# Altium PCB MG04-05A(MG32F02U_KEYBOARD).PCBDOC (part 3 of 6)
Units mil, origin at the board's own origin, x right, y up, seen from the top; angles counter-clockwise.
Board outline 17912.8 x 10422.68 mil, 2 copper layers (Top Layer, Bottom Layer); 623 components, 347 nets, 1816 pads, 821 vias.
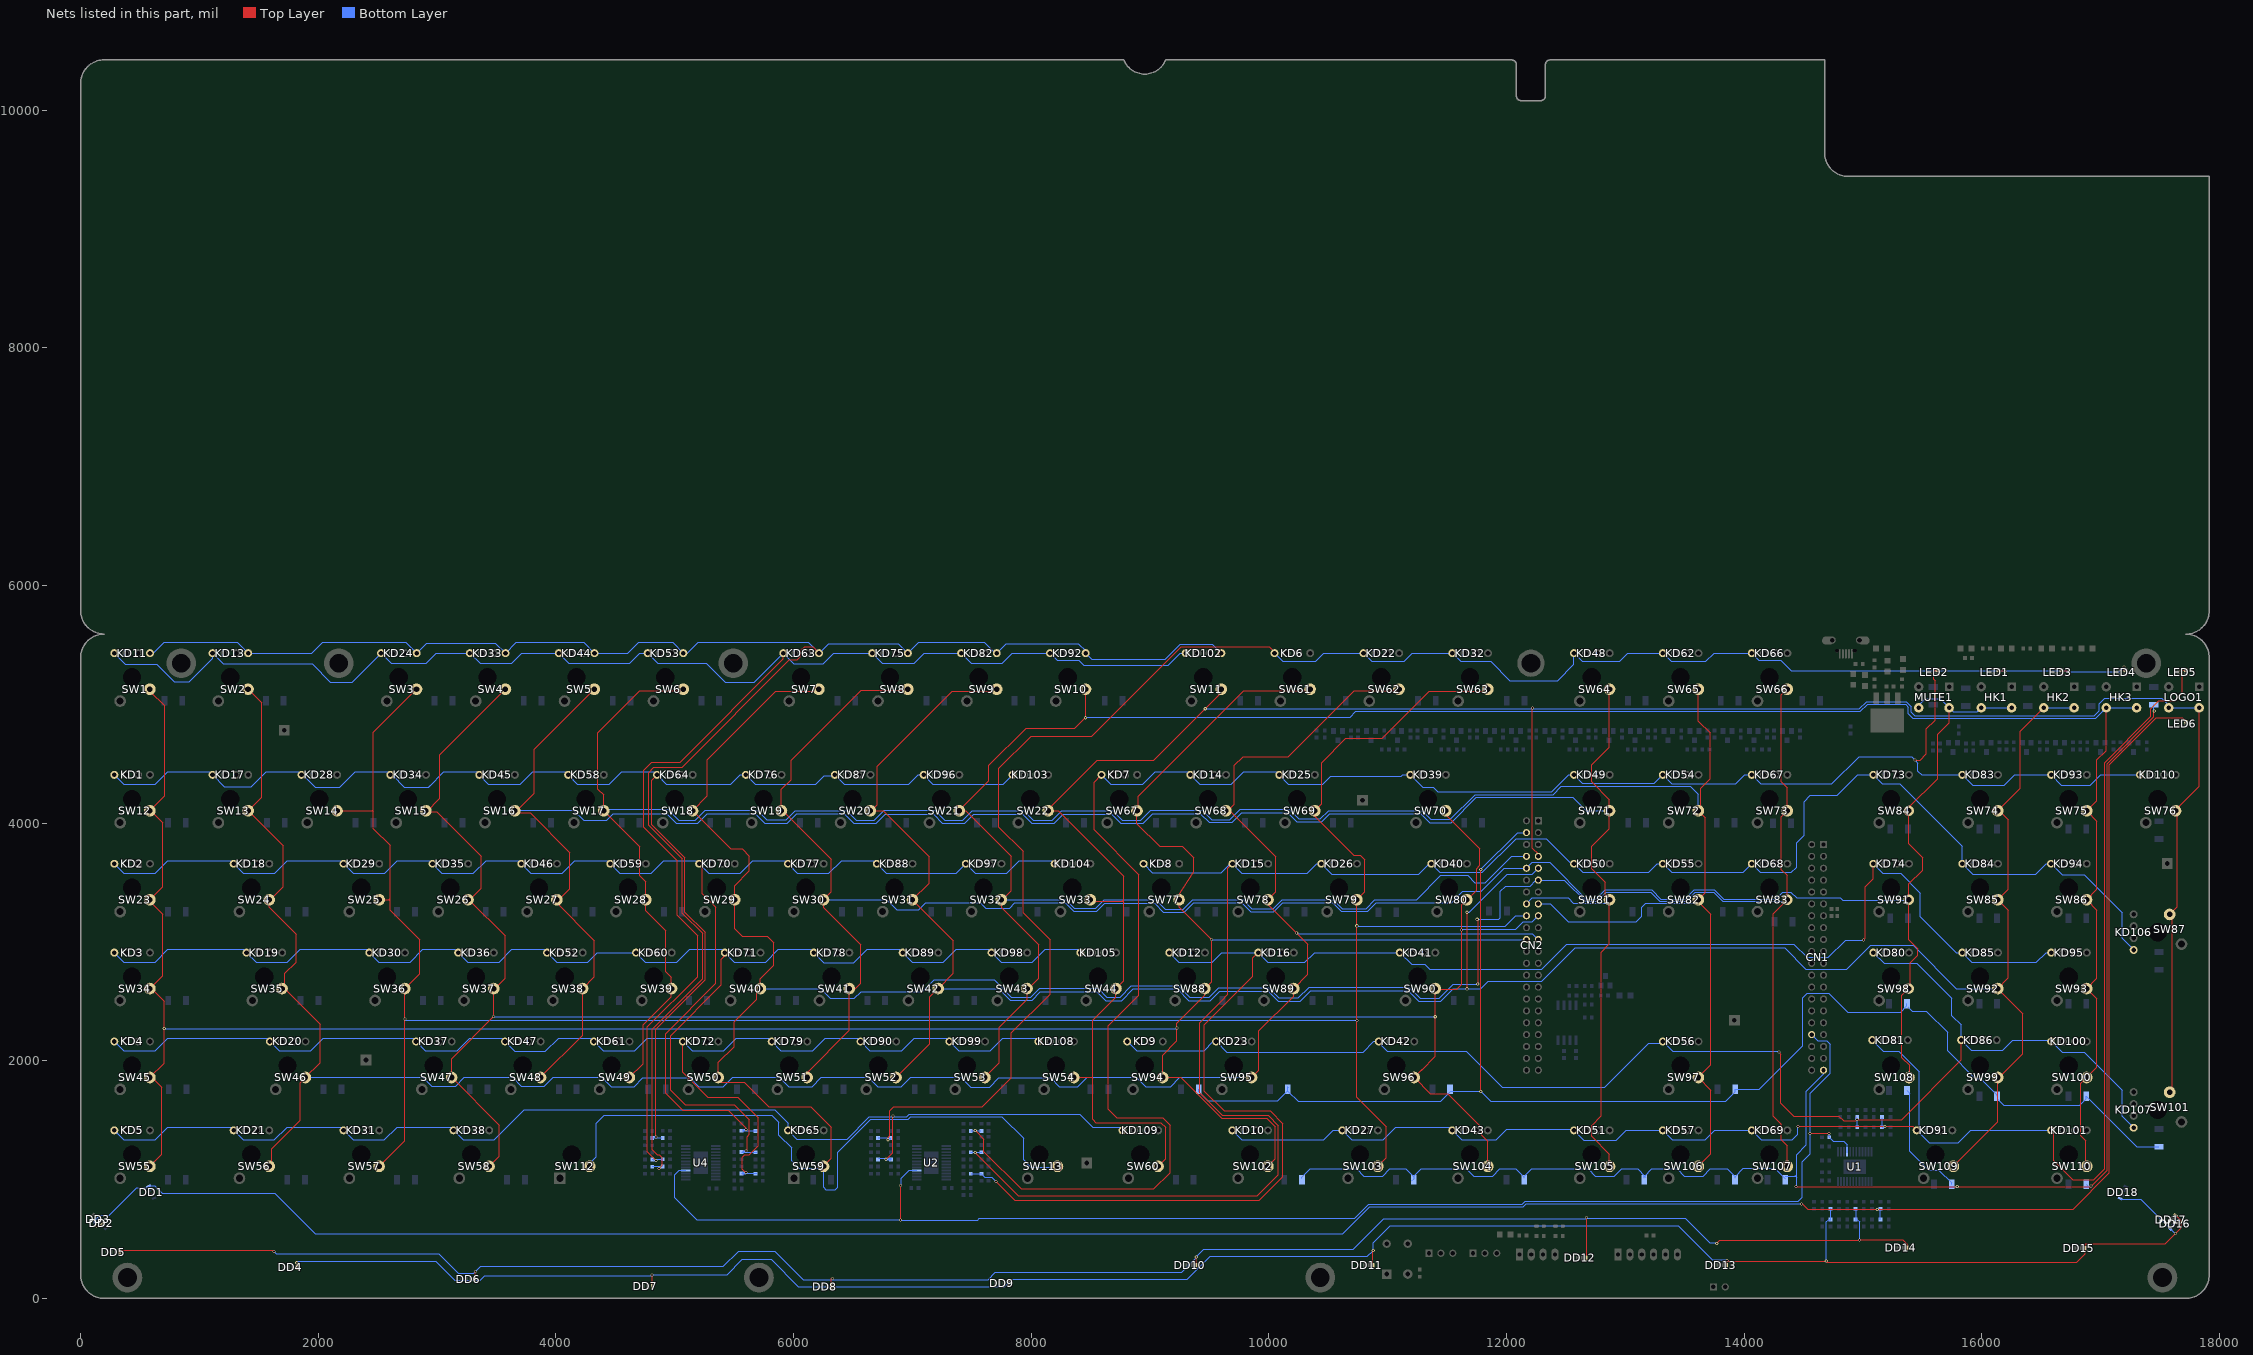
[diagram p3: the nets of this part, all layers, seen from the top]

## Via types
v1: diameter 30, hole 12, Top Layer to Bottom Layer, tented both sides, 273 vias
v2: diameter 26, hole 16, Top Layer to Bottom Layer, tented both sides, 181 vias
v3: diameter 26, hole 12, Top Layer to Bottom Layer, tented both sides, 165 vias
v4: diameter 33, hole 20, Top Layer to Bottom Layer, tented both sides, 61 vias
v5: diameter 25, hole 12, Top Layer to Bottom Layer, tented both sides, 47 vias
v6: diameter 20, hole 12, Top Layer to Bottom Layer, tented both sides, 40 vias
v7: diameter 30, hole 16, Top Layer to Bottom Layer, tented both sides, 30 vias
v8: diameter 28, hole 16, Top Layer to Bottom Layer, tented both sides, 12 vias
v9: diameter 35, hole 20, Top Layer to Bottom Layer, tented both sides, 5 vias
v10: diameter 25, hole 16, Top Layer to Bottom Layer, tented both sides, 3 vias
v11: diameter 40, hole 12, Top Layer to Bottom Layer, tented both sides, 3 vias
v12: diameter 40, hole 20, Top Layer to Bottom Layer, tented both sides, 1 vias

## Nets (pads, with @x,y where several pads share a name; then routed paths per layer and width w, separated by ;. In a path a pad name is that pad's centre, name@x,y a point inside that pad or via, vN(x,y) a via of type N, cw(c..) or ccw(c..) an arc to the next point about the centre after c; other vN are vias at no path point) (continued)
KB_C10: CN2.4 D101.2 D102.2 D103.2 D104.2 D105.2 D106.2 D107.2 D108.2 | length 12067.7
  Top Layer w8: v2(11782,1742.74) v2(11782,3610)
  Bottom Layer w8: D101.2@9408.69,1759.19 9408.69,1739.78 9485.73,1662.74 10073.27,1662.74 D102.2@10158.58,1748.05 ; D102.2@10158.58,1779.28 D102.2@10158.58,1775.43 ; D102.2@10161.56,1776.29 10160.5,1777.35 D102.2@10158.58,1775.43 ; v2(11782,3610) 12092,3920 CN2.4@12167,3920 ; D105.2@15367.95,2480 15367.95,2462.42 15315.34,2409.8 14870.68,2409.8 14712,2568.48 14529.6,2568.48 14492,2530.88 14492,2126.47 14124.72,1759.19 D104.2@13923.88,1759.19 13923.88,1737.74 13844.22,1658.07 11867,1658.07 11782.33,1742.74 v2(11782,1742.74) 11529.74,1742.74 11445.07,1658.07 10245.39,1658.07 10158.58,1744.89 D102.2@10158.58,1748.05 ; D105.2@15377.35,2454.8 15413.52,2418.63 15532.35,2418.63 15710.49,2240.49 15710.49,2082.66 15943.15,1850 15988.47,1850 16127.95,1710.51 D106.2@16127.95,1700 ; D106.2@16127.95,1680.2 16183.15,1625 16823.15,1625 16877.95,1679.8 D107.2@16877.95,1700 17301.51,1276.45 D108.2@17489.6,1276.45 ; D102.2@10158.58,1748.05 D102.2@10158.58,1759.19 D102.2@10158.58,1775.43
KB_C11: CN1.39 D109.2 D110.2 D111.2 D112.2 D113.2 D114.2 D115.2 D116.2 D117.2 D118.2 | length 13746
  Top Layer w8: v2@14437,941.47 v2(15792,941.47) v2@16918.15,941.47 ; v2(16918.15,945) 17053.15,1080 17053.15,4501 17447,4894.85 v2@17447,4944.7
  Bottom Layer w8: D109.2@10277.95,1011.2 10277.95,1020.95 10347,1090 10737,1090 10797,1030 10957,1030 11017,1090 11152,1090 11222,1020 D110.2@11223.57,1020 ; D110.2@11201.85,989.48 D110.2@11220.76,1008.39 ; D110.2@11217.95,1011.2 D110.2@11220.76,1008.39 ; D111.2@12147.2,1020 12077.2,1090 11942.2,1090 11882.2,1030 11722.2,1030 11662.2,1090 11282,1090 11223.57,1031.57 D110.2@11223.57,1020 ; D111.2@12148.36,1010.79 12148.77,1011.2 D111.2@12148.77,1028.29 ; D111.2@12150.29,1028.29 12212,1090 12686.8,1090 12746.8,1030 12906.8,1030 12966.8,1090 13101.8,1090 D112.2@13161.9,1029.9 ; D112.2@13157.95,1011.2 13157.95,1025.95 D112.2@13161.9,1029.9 ; D112.2@13171.8,1020 D112.2@13161.9,1029.9 ; D113.2@13922.76,1011.2 D113.2@13922.76,1024.24 ; D114.2@14344.8,1007.2 14257,1095 13992,1095 13922.76,1025.76 D113.2@13922.76,1024.24 ; D114.2@14344.8,1029.89 14428.23,1029.89 ; v2@14439.6,941.47 14439.6,1021.25 ; 14529.6,1751.25 14558.7,1780.35 ; CN1.39@14667,1920 14667,1888.65 14558.7,1780.35 ; D115.2@15367.95,1750 15393.15,1724.8 15393.15,1240 15553.15,1080 15638.15,1080 15745.79,972.36 D116.2@15745.79,960 ; D116.2@15745.79,941.47 v2(15792,941.47) ; D117.2@16877.95,960 16892.95,945 v2(16918.15,945) ; v2@17447,4950 D118.2@17447,4995.89 ; D110.2@11220.76,1008.39 11223.57,1011.2 D110.2@11223.57,1020 ; D112.2@13161.9,1029.9 13222,1090 13434.87,1090 13494.87,1030 13654.87,1030 13714.87,1090 13857,1090 D113.2@13922.76,1024.24 ; 14428.23,1029.89 14430.96,1029.89 ; 14428.23,1029.89 14429.6,1031.25 ; 14429.6,1031.25 14430.96,1029.89 ; 14429.6,1031.25 14439.6,1041.25 ; 14430.96,1029.89 14439.6,1021.25 ; 14430.96,1029.89 14439.6,1029.89 ; 14439.6,1021.25 14439.6,1029.89 ; 14439.6,1029.89 14439.6,1041.25 ; 14439.6,1041.25 14439.6,1207.25 14523.6,1291.25 14523.6,1745.25 14558.7,1780.35
  other v2: 14434.6,941.47 17449.85,4944.7
KB_R0: CN2.22 SW1.2 SW12.2 SW23.2 SW34.2 SW45.2 SW55.2 SW61.2 SW67.2 SW77.2 SW88.2 SW94.2 SW102.2 | length 21948.4
  Top Layer w10: SW55.2@582.08,1111.19 683.3,1212.4 683.3,1775.17 599.28,1859.19 SW45.2@582.08,1859.19 703.3,1980.4 v2(703.3,2271.47) 703.3,2500.17 596.18,2607.29 SW34.2@582.08,2607.29 692,2717.2 692,3231.47 582.08,3341.38 SW23.2@582.08,3354.89 692,3464.8 692,4001.47 590.18,4103.29 SW12.2@582.08,4103.29 707,4228.2 707,4986.47 582.08,5111.38 SW1.2@582.08,5126.89 ; SW67.2@8889.2,4103.29 8889.2,3996.22 9079.6,3805.81 9269.6,3805.81 9369.16,3706.26 9369.16,3592 SW77.2@9236.76,3389.59 ; SW67.2@8898.13,4103.29 8898.13,4224.35 9789.6,5115.81 10334.82,5115.81 SW61.2@10345.89,5126.89 ; SW77.2@9243.57,3354.89 9243.57,3293.43 v8(9517,3020) 9519.6,3017.4 9519.6,2666.78 SW88.2@9460.11,2607.29 9460.11,2550.51 9225,2315.41 9225,2167 9105.75,2047.75 SW94.2@9105.75,1859.19 9258.81,1859.19 9603,1515 9983.15,1515 10053.15,1445 10053.15,1173.76 SW102.2@9990.58,1111.19
  Bottom Layer w8: v2@703.3,2270 v2@9227,2270 ; v8(9517,3020) CN2.22@12167,3020
  other v2: 9227,2275
KB_R1: CN2.21 SW2.2 SW13.2 SW24.2 SW35.2 SW46.2 SW56.2 SW62.2 SW68.2 SW78.2 SW89.2 SW95.2 | length 20193.8
  Top Layer w10: SW2.2@1408.39,5126.89 1522.28,5013 1522.28,4216.59 SW13.2@1408.98,4103.29 1703.15,3809.11 1703.15,3463.59 1586.03,3346.47 1586.03,3292.12 1813.15,3065 1813.15,2830 1718.15,2735 SW35.2@1718.15,2607.29 ; SW56.2@1586.04,1111.19 1608.15,1133.3 1608.15,1260 1848.15,1500 1848.15,1816.19 SW46.2@1891.15,1859.19 2016.74,1984.78 2016.74,2306.42 1715.87,2607.29 SW35.2@1694.3,2607.29 ; SW68.2@9637.27,4103.29 SW68.2@9654.4,4103.29 ; SW68.2@9649.6,4098.48 SW68.2@9654.4,4103.29 ; SW95.2@9853.78,1859.19 9916,1921.41 9916,2251.86 10208.14,2544 SW89.2@10208.14,2607.29 10328.15,2727.3 10328.15,2980 v8(10233.31,3074.84) 9991.6,3316.55 SW78.2@9991.6,3354.89 10058.15,3421.44 10058.15,3715 9669.86,4103.29 SW68.2@9654.4,4103.29 ; SW62.2@11094.08,5126.89 11082.19,5115 10718.15,5115 10161.63,4558.48 9781.78,4558.48 9709.6,4486.31 9709.6,4158.48 SW68.2@9654.4,4103.29
  Bottom Layer w8: SW46.2@1912,1870 1922,1860 2879.6,1860 2954.6,1785 3155.07,1785 3230.07,1860 3634.6,1860 3709.6,1785 3902,1785 3977,1860 4384.6,1860 4464.6,1780 4657,1780 4732,1855 5129.6,1855 5201.9,1782.7 5409.7,1782.7 5487,1860 5879.6,1860 5956.9,1782.7 6154.7,1782.7 6232,1860 6629.6,1860 6706.9,1782.7 6907.6,1782.7 6984.9,1860 7407,1860 7489.3,1777.7 7649.7,1777.7 7727,1855 8162,1855 8237,1780 8392,1780 8472,1860 8882,1860 8962,1780 9172,1780 9251.19,1859.19 SW95.2@9853.78,1859.19 ; v8(10233.31,3074.84) 10238.15,3070 12110,3070 ; 12095,3070 12110,3070 ; CN2.21@12267,3020 12217,3070 12110,3070
KB_R2: CN2.18 SW3.2 SW14.2 SW25.2 SW36.2 SW57.2 SW63.2 SW69.2 SW79.2 SW103.2 | length 19909.6
  Top Layer w8: 2461.08,4097.04 2454.83,4103.29 2462.6,4111.05 ; 2601.08,3347.04 2591.81,3356.31 2603.3,3367.79
  Top Layer w10: SW14.2@2156.86,4103.29 2454.83,4103.29 2462.6,4103.29 ; SW25.2@2498.84,3356.31 SW25.2@2511.42,3356.31 ; SW57.2@2511.24,1111.19 2727.76,1327.71 v2(2727.76,2350) SW36.2@2727.76,2607.29 2852,2731.53 2852,3016.31 2603.3,3265.01 2603.3,3356.31 ; SW25.2@2511.42,3354.89 SW25.2@2511.42,3356.31 ; SW103.2@10915.78,1111.19 10988.15,1183.56 10988.15,1445 10739.63,1693.52 v2(10739.63,2340) v8(10739.63,3135) SW79.2@10739.63,3354.89 10806.12,3421.38 10806.12,3690.88 10768,3729 10714.08,3729 10385.26,4057.82 SW69.2@10385.26,4103.29 10443.15,4161.18 10443.15,4508.34 10648.3,4713.48 10953.48,4713.48 11350,5110 11825.12,5110 SW63.2@11842,5126.89 ; 2462.6,4103.29 2462.6,4111.05 2462.6,4763.11 SW3.2@2812.98,5113.48 ; 2462.6,4103.29 2462.6,3952.16 2603.3,3811.47 2603.3,3367.79 2603.3,3356.31 ; SW25.2@2511.42,3356.31 2591.81,3356.31 2603.3,3356.31 ; SW3.2@2812.98,5113.48 SW3.2@2826.38,5126.89 2826.38,5113.48 SW3.2@2812.98,5113.48
  Bottom Layer w8: v2(2727.76,2350) 2737.76,2340 v2(10739.63,2340) ; v8@10739.63,3130 11987,3130 12077,3220 CN2.18@12167,3220 CN2.18@12137,3220
KB_R3: CN2.17 SW4.2 SW15.2 SW26.2 SW37.2 SW47.2 SW58.2 SW70.2 SW80.2 SW90.2 SW96.2 SW104.2 | length 17587.8
  Top Layer w10: SW15.2@2904.97,4103.29 2904.97,4091.47 SW15.2@2910.88,4097.38 ; SW26.2@3267,3356.47 SW26.2@3272.14,3351.32 ; SW58.2@3436.44,1111.19 SW58.2@3446.85,1121.6 ; SW58.2@3446.85,1120.7 SW58.2@3446.85,1121.6 ; SW37.2@3475.83,2607.29 SW37.2@3475.83,2596.47 ; SW4.2@3574.38,5126.89 3023.3,4575.8 3023.3,4209.79 SW15.2@2910.88,4097.38 ; 11284.07,1921.36 11399.08,2036.38 v2(11399.08,2370) SW90.2@11399.08,2603.48 ; 11289.6,1926.9 SW96.2@11221.89,1859.19 11357.6,1723.48 11504.6,1723.48 11792.16,1435.92 11792.16,1372.3 11840.98,1323.48 SW104.2@11840.98,1111.19 ; SW90.2@11399.08,2607.29 SW90.2@11399.08,2603.48 ; SW70.2@11487.7,4103.29 11487.7,4070.76 11774.6,3783.87 11774.6,3643.48 11746.85,3615.73 11746.85,3436.95 SW80.2@11664.79,3354.89 11622,3312.1 v2(11622,3100) 11622,2645.88 11579.6,2603.48 SW90.2@11399.08,2603.48 ; SW15.2@2910.88,4097.38 2911.95,4096.31 2998.46,4096.31 3372,3722.76 3372,3451.18 SW26.2@3272.14,3351.32 ; SW26.2@3267.5,3346.69 SW26.2@3259.3,3354.89 3259.3,3338.48 SW26.2@3267.5,3346.69 ; SW26.2@3267.5,3346.69 SW26.2@3272.14,3351.32 ; SW26.2@3272.14,3351.32 3572,3051.47 3572,2692.63 3481.24,2601.88 SW37.2@3475.83,2596.47 ; SW58.2@3446.85,1121.6 3523.3,1198.04 3523.3,1457.36 SW47.2@3121.47,1859.19 3121.47,2018.32 v2(3475.83,2372.68) SW37.2@3475.83,2596.47
  Bottom Layer w8: v2@3475.83,2370 v2(11399.08,2370) ; v2@11622,3105 12077,3105 12142,3170 12217,3170 CN2.17@12267,3220
KB_R4: CN2.16 SW5.2 SW16.2 SW27.2 SW38.2 SW48.2 SW64.2 SW71.2 SW81.2 SW105.2 | length 19299.2
  Top Layer w10: SW16.2@3652,4086.47 SW16.2@3668.82,4103.29 ; SW16.2@3652.96,4103.29 SW16.2@3668.82,4103.29 ; SW48.2@3869.53,1859.19 4223.86,2213.52 SW38.2@4223.86,2607.29 4323.3,2706.72 4323.3,3009.85 3992.8,3340.35 SW27.2@4007.33,3354.89 ; SW27.2@4007,3336.47 4117,3446.47 4117,3751.31 3781.84,4086.47 3686.68,4086.47 3669.86,4103.29 SW16.2@3668.82,4103.29 ; SW5.2@4322.38,5126.89 3817,4621.5 3817,4251.47 SW16.2@3668.82,4103.29 ; SW105.2@12865.58,1111.19 12865.58,1213.99 12716.77,1362.8 12716.77,1455 12797,1535.23 12797,2915 12865.58,2983.58 SW81.2@12865.58,3354.89 12829.6,3390.87 12829.6,3503.48 12716.77,3616.32 12716.77,3805.65 12865.59,3954.47 12865.59,4197.5 12716.77,4346.32 12716.77,4490.96 12865.58,4639.78 SW64.2@12865.58,5126.89
  Bottom Layer w8: SW16.2@3652.96,4103.29 3659.68,4110 4147,4110 4232,4025 4428.15,4025 4483.15,4080 4932,4080 5012,4000 5192,4000 5272,4080 5677,4080 5757,4000 5947,4000 6027,4080 6427,4080 6507,4000 6697,4000 6772,4075 7177,4075 7252,4000 7442,4000 7517,4075 7927,4075 8002,4000 8192,4000 8267,4075 8677,4075 8752,4000 8942,4000 9022,4080 9422,4080 9497,4005 9692,4005 9772,4085 10157,4085 10232,4010 10443.96,4010 10511.77,4077.8 11278.97,4077.8 11353.29,4003.48 11532.45,4003.48 11746.16,4217.2 12556.27,4217.2 12670.18,4103.29 SW71.2@12865.58,4103.29 ; CN2.16@12167,3320 12217,3370 12517,3370 12562,3325 12835.7,3325 SW81.2@12865.58,3354.89
KB_R5: CN2.15 SW6.2 SW17.2 SW28.2 SW39.2 SW49.2 SW65.2 SW72.2 SW82.2 SW97.2 SW106.2 | length 20074.3
  Top Layer w10: SW17.2@4409.1,4103.29 SW17.2@4409.1,4096.31 ; SW49.2@4617.54,1859.19 4735,1976.64 4735,2301.85 4971.91,2538.76 SW39.2@4971.91,2607.29 4971.91,2702.09 4923.09,2750.91 4923.09,3092.91 4755.32,3260.68 SW28.2@4755.32,3354.89 4755.32,3507.83 4706.51,3556.65 4706.51,3798.91 SW17.2@4409.1,4096.31 ; SW6.2@5070.39,5126.89 5056.98,5113.48 4704.6,5113.48 4352.17,4761.06 4352.17,4285.37 4400.99,4236.55 SW17.2@4400.99,4103.29 4402.13,4103.29 SW17.2@4409.1,4096.31 ; SW106.2@13613.63,1111.19 13719.6,1217.16 13719.6,1753.24 SW97.2@13613.65,1859.19 13719.6,1965.14 13719.6,3233.48 13613.65,3339.43 SW82.2@13613.65,3354.89 13671.77,3413 13671.77,4045.17 SW72.2@13613.65,4103.29 ; SW65.2@13613.65,5126.85 13613.65,4858.13 13712.6,4759.18 13712.6,4374.45 13633.15,4295 SW72.2@13633.15,4122.78
  Bottom Layer w8: SW17.2@4400.99,4103.29 4412.71,4115 4942,4115 5032,4025 5172,4025 5257,4110 5692,4110 5772,4030 5937,4030 6012,4105 6447,4105 6527,4025 6677,4025 6762,4110 7187,4110 7272,4025 7422,4025 7502,4105 7937,4105 8017,4025 8177,4025 8257,4105 8687,4105 8767,4025 8922,4025 9007,4110 9437,4110 9517,4030 9672,4030 9757,4115 10172,4115 10252,4035 10432,4035 10502,4105 11289.57,4105 11361.77,4032.8 11527.61,4032.8 11734.81,4240 12390.53,4240 12460.53,4310 13547,4310 13613.65,4243.35 SW72.2@13613.65,4103.29 ; CN2.15@12267,3320 12367,3320 12517,3170 13092,3170 13137,3215 13137,3290 13172,3325 13583.76,3325 SW82.2@13613.65,3354.89
KB_R6: CN2.11 SW7.2 SW18.2 SW29.2 SW40.2 SW50.2 SW59.2 SW66.2 SW73.2 SW83.2 SW107.2 SW112.2 SW113.2 | length 26218.9
  Top Layer w10: SW7.2@6211.77,5097.8 SW7.2@6211.77,5117.8 ; SW7.2@6212.39,5126.89 6193.98,5108.48 5849.6,5108.48 5274.6,4533.48 5274.6,4228.9 SW18.2@5148.99,4103.29 5469.47,3782.8 5566.77,3782.8 5626.77,3722.8 5626.77,3597.8 5503.4,3474.43 SW29.2@5503.4,3354.89 5503.4,3112.02 5569.6,3045.81 5779.6,3045.81 5833.15,2992.26 5833.15,2803.15 5719.94,2689.94 SW40.2@5719.94,2607.29 5688,2575.35 5688,2519 5498.15,2329.15 5498.15,2119.15 5365.58,1986.58 SW50.2@5365.58,1859.19 5365.58,1818.28 5584.43,1818.28 5789.22,1613.48 6144.67,1613.48 6318.15,1440 6318.15,1177.93 SW59.2@6251.41,1111.19 ; v8(11752,3190) 11762,3180 v2@11762,2650 ; SW107.2@14361.65,1111.19 14361.65,1285.35 14312,1335 14312,1464.77 14243.29,1533.48 14243.29,3236.53 SW83.2@14361.65,3354.89 ; 14361.65,3478.35 SW83.2@14361.65,3354.89 ; SW66.2@14361.65,5126.89 14312.87,5078.11 14312.87,4347.8 14361.65,4299.02 SW73.2@14361.65,4103.29 14312.87,4054.51 14312.87,3609.13 14361.65,3560.35 SW83.2@14361.65,3354.89
  Bottom Layer w8: SW40.2@5719.94,2607.29 6227,2607.29 6309.29,2525 6512,2525 6567,2580 7082,2580 7182,2680 7687,2680 7832,2535 7997,2535 8072,2610 8563.47,2610 8637,2536.47 8747,2536.47 8840.53,2630 9237,2630 9332,2535 9497,2535 9577,2615 9997,2615 10082,2530 10247,2530 10337,2620 11177,2620 11272,2525 11432,2525 11552,2645 v2(11757,2645) ; v8(11752,3190) 11932,3190 11947,3205 11947,3425 11992,3470 12197,3470 CN2.11@12247,3520 ; CN2.11@12267,3520 12487,3520 12664.68,3342.32 12759.32,3342.32 12837,3420 13212,3420 13289.68,3342.32 13509.32,3342.32 13587,3420 13742,3420 13819.68,3342.32 14242,3342.32 ; 14257,3342.32 14242,3342.32 ; SW83.2@14361.65,3354.89 14349.09,3342.32 14242,3342.32
  Bottom Layer w10: SW112.2@4282.9,1111.19 4282.9,1136.75 4336.85,1190.7 4336.85,1475.7 4404.4,1543.25 5814.3,1543.25 5875.41,1482.13 5875.41,1373.05 5982,1266.47 5982,1156.47 6042.77,1095.7 SW59.2@6235.92,1095.7 ; SW59.2@6251.41,1111.19 SW59.2@6235.92,1095.7 ; SW59.2@6251.85,1111.19 SW59.2@6251.85,1095.7 ; SW59.2@6261.85,1095.7 SW59.2@6251.85,1095.7 ; SW113.2@8236.85,1105.7 7996.85,1105.7 7936.85,1165.7 7936.85,1346.62 7752.77,1530.7 6986.85,1530.7 6962.62,1506.47 6647.62,1506.47 6372,1230.85 6372,936.47 6351.23,915.7 6271.85,915.7 6251.85,935.7 SW59.2@6251.85,1095.7 ; SW59.2@6235.92,1095.7 SW59.2@6251.85,1095.7
KB_R7: CN2.10 HK1.2 HK1.4 MUTE1.2 MUTE1.4 SW8.2 SW19.2 SW30.2 SW41.2 SW51.2 SW84.2 SW91.2 SW98.2 SW108.2 | length 18775
  Top Layer w10: SW51.2@6113.61,1859.19 6113.61,1900.7 6467.97,2255.06 SW41.2@6467.97,2607.29 6519.89,2607.29 6563.3,2650.7 6563.3,2977.16 6251.39,3289.07 SW30.2@6251.39,3354.89 6318.15,3421.65 6318.15,3695 5909.86,4103.29 SW19.2@5897.02,4103.29 5897.02,4283.87 5978.15,4365 5978.15,4527.03 6569.6,5118.48 6951.65,5118.48 SW8.2@6960.05,5126.89 ; SW108.2@15385.47,1859.19 15391.64,1865.36 15391.64,1960.36 15327,2025 15327,2549.44 SW98.2@15384.84,2607.29 15398.29,2620.74 15398.29,2826.6 15458.17,2886.48 15458.17,2944.48 15384.49,3018.16 SW91.2@15384.49,3354.89 15384.49,3487.49 15501.29,3604.29 15501.29,3708.28 15385.27,3824.3 SW84.2@15385.27,4103.29 15385.27,4131.46 15627.29,4373.48 15627.29,4748.33 15724,4845.04 MUTE1.2@15724,4970
  Bottom Layer w8: SW30.2@6251.39,3354.89 6782.11,3354.89 6867,3270 7052,3270 7112,3330 7572,3330 7617,3285 7817,3285 7862,3330 8287,3330 8357,3260 8552,3260 8617,3325 9037,3325 9112,3250 9287,3250 9367,3330 9772,3330 9847,3255 10042,3255 10117,3330 10537,3330 10607,3260 10832,3260 10902,3330 11537,3330 11632,3425 11787,3425 11982,3620 CN2.10@12167,3620 12217,3670 12362,3670 12672,3360 12752,3360 12829.68,3437.68 13219.32,3437.68 13297,3360 13502,3360 13579.68,3437.68 13749.32,3437.68 13827,3360 14242,3360 ; 14257,3360 14242,3360 ; SW91.2@15384.49,3354.89 15379.6,3350 14827,3350 14807,3370 14442,3370 14392,3420 14322,3420 14262,3360 14242,3360 ; MUTE1.4@15468,4970 15468,4991.85 15521.85,5045.7 15648.3,5045.7 MUTE1.2@15724,4970 15759,4935 15959,4935 HK1.4@15994,4970 HK1.2@16250,4970
KB_R8: CN2.9 HK2.2 HK2.4 SW9.2 SW20.2 SW31.2 SW42.2 SW52.2 SW74.2 SW85.2 SW92.2 SW99.2 SW109.2 | length 20471.8
  Top Layer w10: SW20.2@6645.06,4103.29 6754.8,4103.29 7139.6,3718.48 7139.6,3495.03 SW31.2@6999.46,3354.89 7343.3,3011.05 7343.3,2734.58 SW42.2@7216,2607.29 7146.85,2538.14 7146.85,2144.4 SW52.2@6861.64,1859.19 ; SW20.2@6655,4117 6668.12,4117 6704.6,4153.48 6704.6,4478.48 7334.6,5108.48 7689.73,5108.48 SW9.2@7708.13,5126.89 ; v8@11667,2615 v8(11667,3250) ; SW109.2@15759.49,1111.19 16133.5,1485.2 SW99.2@16133.5,1849.8 ; SW99.2@16133.5,1859.19 SW99.2@16133.5,1849.8 ; HK2.4@16520,4970 16322,4772 16322,4291.76 16196.6,4166.36 16140.12,4109.88 16223.15,4026.85 16223.15,3444.69 SW85.2@16133.34,3354.89 16223.15,3265.08 16223.15,2696.91 SW92.2@16133.52,2607.29 16343.3,2397.51 16343.3,2059.6 SW99.2@16133.5,1849.8
  Bottom Layer w8: SW52.2@6861.64,1859.19 SW52.2@6872.45,1870 ; SW42.2@7216,2607.29 7724.71,2607.29 7822,2510 8007,2510 8077,2580 8551.04,2580 8624.57,2506.47 8759.43,2506.47 8857.96,2605 9227,2605 9327,2505 9507,2505 9587,2585 9992,2585 10077,2500 10262,2500 10352,2590 11172,2590 11262,2500 11447,2500 11552,2605 v8(11667,2605) 11782,2605 11847,2670 12297,2670 12577,2950 14339,2950 14519,2770 14862,2770 15062.7,2970.7 15421.3,2970.7 15784.71,2607.29 SW92.2@16133.52,2607.29 ; v8(11667,3250) 11687,3250 12007,3570 12217,3570 CN2.9@12267,3620 ; HK2.4@16520,4970 HK2.2@16776,4970
KB_R9: CN2.8 HK3.2 HK3.4 SW10.2 SW21.2 SW32.2 SW43.2 SW53.2 SW75.2 SW86.2 SW93.2 SW100.2 SW110.2 | length 22609.9
  Top Layer w10: SW53.2@7609.67,1859.19 7731.75,1981.26 7731.75,2283.6 7964.03,2515.88 SW43.2@7964.03,2596.47 ; SW43.2@7964.03,2607.29 SW43.2@7964.03,2596.47 ; v2@8456.16,4891.47 SW10.2@8456.16,5126.89 ; v2@8457,4891.47 8365.53,4800 7955.53,4800 7643.15,4487.62 7643.15,4357.62 7390.98,4105.44 SW21.2@7393.13,4103.29 7450.18,4103.29 7831.6,3721.86 7831.6,3430.57 SW32.2@7751.71,3350.68 ; SW110.2@16881.54,1111.19 16874.22,1118.51 16874.22,1326.98 16832.72,1368.48 16832.72,1810.55 SW100.2@16881.36,1859.19 16968.15,1945.98 16968.15,2520.7 SW93.2@16881.57,2607.29 16968.15,2693.87 16968.15,3267.3 SW86.2@16880.57,3354.89 16968.15,3442.47 16968.15,4016.48 SW75.2@16881.35,4103.29 16968.15,4190.09 16968.15,4533 17046,4610.85 HK3.4@17046,4970 ; SW32.2@7751.71,3350.68 SW32.2@7747.5,3354.89 7747.5,3346.47 SW32.2@7751.71,3350.68 ; SW32.2@7751.71,3350.68 7751.71,3286.75 8062,2976.47 8062,2694.43 SW43.2@7964.03,2596.47
  Bottom Layer w8: SW32.2@7747.5,3354.89 7747.62,3355 8292,3355 8362,3285 8542,3285 8612,3355 9047,3355 9127,3275 9277,3275 9357,3355 9782,3355 9857,3280 10037,3280 10112,3355 10542,3355 10617,3280 10817,3280 10892,3355 11242,3355 11447,3560 11672,3560 11732,3500 11822,3500 12042,3720 CN2.8@12167,3720 ; v2@8452,4891.47 10683.47,4891.47 10732,4940 14977.27,4940 15037.96,5000.7 15356.85,5000.7 15381.85,4975.7 15381.85,4920.7 15419.06,4883.48 16959.48,4883.48 HK3.4@17046,4970 HK3.2@17302,4970
  other v2: 8457,4886.47
KB_R10: CN2.7 LOGO1.2 LOGO1.4 SW11.2 SW22.2 SW33.2 SW44.2 SW54.2 SW60.2 SW76.2 SW87.2 SW101.2 | length 19667.1
  Top Layer w8: 8516.08,1852.04 8508.93,1859.19 8517,1867.25 ; 8776.08,3332.04 8766.12,3342 8777,3352.88 ; SW101.2@17579.4,1735.19 17599.6,1755.39 17599.6,3211.25 SW87.2@17579.6,3231.25 17644.6,3296.25 SW76.2@17644.6,4088.1 ; SW76.2@17639.68,4121.33 17828,4309.65 LOGO1.2@17828,4970
  Top Layer w10: SW22.2@8159.86,4103.29 SW22.2@8141.12,4103.29 ; SW54.2@8357.71,1859.19 8508.93,1859.19 8517,1859.19 ; SW33.2@8496.53,3342 8766.12,3342 8777,3342 ; SW60.2@9066.38,1111.19 9129.36,1174.17 9129.36,1438.64 9088,1480 8543.3,1480 8517,1506.3 8517,1859.19 ; SW11.2@9597.98,5126.89 9597.98,5095.77 9030.69,4528.48 8554.6,4528.48 8129.4,4103.29 SW22.2@8141.12,4103.29 ; v2@12217,4958 12217,3790 12267,3740 CN2.7@12267,3720 ; SW22.2@8141.12,4103.29 8225.18,4103.29 8777,3551.47 8777,3352.88 8777,3342 ; 8517,1859.19 8517,1867.25 8517,2341.47 8712.02,2536.49 SW44.2@8712.02,2607.29 8777,2672.26 8777,3342
  Bottom Layer w8: v2(9463.95,4962) 14968.15,4962 15028.85,5022.7 15364.85,5022.7 15406.85,4980.7 15406.85,4930.7 15434.06,4903.48 16944.64,4903.48 16987,4945.85 16987,5004.15 17031.85,5049 17513,5049 17572,4990 LOGO1.4@17572,4970 LOGO1.2@17828,4970 ; SW76.2@17639.68,4121.33 17639.68,4093.02 SW76.2@17644.6,4088.1
  other v2: 12217,4970
LE: CN1.34 R61.2 U1.4 U2.4 U4.4 | length 12503.4
  Top Layer w8: v2(6900,658.48) v2(6900,949.89) ; v2@14552.24,1388.48 v2(14553.29,1388.48) v2(14714.64,1388.48)
  Bottom Layer w8: U4.4@5094.02,1076.66 5036.77,1076.66 5000,1039.89 5000,846.47 5182.98,663.48 6900,663.48 6905,658.48 7402.88,658.48 7548.29,658.48 7563.29,673.48 10721.17,673.48 10839.15,791.47 12130.43,791.47 12157.43,818.47 13827,818.47 ; v2@6905,954.89 6905,1009.89 6971.77,1076.66 U2.4@7034.02,1076.66 ; 13866,818.47 13827,818.47 ; CN1.34@14567,2220 14617,2170 14692,2170 14722,2140 14722,1895 14554.6,1727.6 14554.6,1215.89 14487.6,1148.89 14487.6,851.47 14454.6,818.47 13827,818.47 ; v2(14714.64,1388.48) R61.2@14714.64,1356.75 14747.91,1323.48 14836.52,1323.48 14866.02,1293.98 U1.4@14866.02,1234.89 U1.4@14866.02,1225.98
LED_B0: C48.1 KD11.4 KD13.4 KD24.4 KD33.4 KD44.4 KD53.4 KD63.4 KD75.4 KD82.4 KD92.4 KD102.4 R117.1 | length 15547.3
  Top Layer w8: v2(4842.57,1158.92) 4769,1232.48 4769,2284.83 5191.54,2707.38 5191.54,3053.38 5019.58,3225.33 5019.58,3683.33 4736.63,3966.29 4736.63,4442.85 4807.21,4513.43 5045.43,4513.43 5913.57,5381.57 KD63.4@5913.57,5429.8
  Bottom Layer w8: KD11.4@283.27,5429.8 374.59,5338.48 638.52,5338.48 785.53,5191.47 912.16,5191.47 1109.57,5388.87 KD13.4@1109.57,5429.8 1199.37,5340 1948.31,5340 2101.84,5186.47 2284.22,5186.47 KD24.4@2527.56,5429.8 2613.88,5343.48 2906.63,5343.48 2993.15,5430 3275.37,5430 KD33.4@3275.56,5429.8 3361.88,5343.48 3626.63,5343.48 3712.95,5429.8 KD44.4@4023.56,5429.8 4107.38,5345.98 4620.61,5345.98 4704.43,5429.8 KD53.4@4771.57,5429.8 4855.39,5345.98 5263.78,5345.98 5423.3,5186.47 5670.23,5186.47 KD63.4@5913.57,5429.8 6002.12,5341.25 6249.25,5341.25 6337.8,5429.8 KD75.4@6661.23,5429.8 6746.3,5344.73 7013.08,5344.73 7098.15,5429.8 KD82.4@7409.31,5429.8 7494.38,5344.73 7753.73,5344.73 7838.8,5429.8 KD92.4@8157.35,5429.8 8217.35,5369.8 8400.49,5369.8 8441.02,5329.28 9154.43,5329.28 9254.95,5429.8 KD102.4@9299.16,5429.8 ; C48.1@4810.92,1170.31 R117.1@4896,1170.31
  Bottom Layer w12: C48.1@4822.87,1158.92 v2(4842.57,1158.92)
LED_B1: C54.1 KD1.4 KD17.4 KD28.4 KD34.4 KD45.4 KD58.4 KD64.4 KD76.4 KD87.4 KD96.4 KD103.4 R123.1 | length 11972.3
  Top Layer w8: KD58.4@4102.18,4406.2 KD58.4@4108.13,4400.25 ; v2@4839.9,1362.17 4839.9,2266.65 5254.53,2681.28 5254.53,3079.47 5082.57,3251.43 5082.57,3709.43 4804.6,3987.4 4804.6,4360.64 KD64.4@4850.17,4406.2 ; v2(4842.57,1358.92) v2@4842.57,1362.17
  Bottom Layer w8: KD1.4@281.07,4408.4 KD1.4@283.27,4406.2 360.99,4328.48 629.29,4328.48 734.21,4433.4 1082.96,4433.4 KD17.4@1110.16,4406.2 ; KD17.4@1107.96,4408.4 KD17.4@1110.16,4406.2 ; KD28.4@1855.84,4408.4 KD28.4@1858.04,4406.2 ; KD34.4@2603.95,4408.4 KD34.4@2606.15,4406.2 ; 2931.5,4307.8 3057.09,4433.4 3326.95,4433.4 KD45.4@3354.14,4406.2 ; 2937.31,4313.62 2927.18,4303.48 2723.29,4303.48 2620.57,4406.2 KD34.4@2606.15,4406.2 ; KD45.4@3351.95,4408.4 KD45.4@3354.14,4406.2 ; KD58.4@4099.98,4408.4 KD58.4@4102.18,4406.2 ; C54.1@4812,1350.31 R123.1@4896,1350.31 ; KD64.4@4847.97,4408.4 KD64.4@4850.17,4406.2 ; KD76.4@5596,4408.4 KD76.4@5598.2,4406.2 ; KD87.4@6344.04,4408.4 KD87.4@6346.24,4406.2 ; KD96.4@7092.12,4408.4 KD96.4@7094.31,4406.2 ; KD103.4@7842.3,4406.2 7764.58,4328.48 7172.03,4328.48 KD96.4@7094.31,4406.2 ; KD17.4@1110.16,4406.2 1208.56,4307.8 1435.5,4307.8 1561.1,4433.4 1830.84,4433.4 KD28.4@1858.04,4406.2 ; KD28.4@1858.04,4406.2 1870.57,4406.2 1973.29,4303.48 2179.06,4303.48 2308.98,4433.4 2578.95,4433.4 KD34.4@2606.15,4406.2 ; KD45.4@3354.14,4406.2 3431.86,4328.48 3700.17,4328.48 3805.09,4433.4 4074.98,4433.4 KD58.4@4102.18,4406.2 ; KD58.4@4102.18,4406.2 4179.9,4328.48 4448.2,4328.48 4553.12,4433.4 4822.97,4433.4 KD64.4@4850.17,4406.2 ; KD64.4@4850.17,4406.2 4927.89,4328.48 5472.48,4328.48 5550.2,4406.2 KD76.4@5598.2,4406.2 ; KD76.4@5598.2,4406.2 5675.92,4328.48 6187.48,4328.48 6256,4397 6337.04,4397 KD87.4@6346.24,4406.2 ; KD87.4@6346.24,4406.2 6423.96,4328.48 6970.48,4328.48 7048.2,4406.2 KD96.4@7094.31,4406.2
  Bottom Layer w12: C54.1@4825,1360 v2@4844.69,1360
LED_B2: C56.1 KD2.4 KD18.4 KD29.4 KD35.4 KD46.4 KD59.4 KD70.4 KD77.4 KD88.4 KD97.4 KD104.4 R124.2 | length 11916.9
  Top Layer w8: KD70.4@5204.58,3657.8 5230,3632.38 5230,3406 5345.75,3290.25 5345.75,2652.5 4922.32,2229.07 4922.32,1727.68 5065,1585 5448.71,1585 5598.15,1435.56 v2(5598.15,1420)
  Bottom Layer w8: KD2.4@283.27,3657.8 362.59,3578.48 627.69,3578.48 734.21,3685 1260.01,3685 KD18.4@1287.21,3657.8 ; KD18.4@1285.01,3660 KD18.4@1287.21,3657.8 ; KD29.4@2210.4,3660 KD29.4@2212.6,3657.8 ; KD35.4@2958.29,3660 KD35.4@2960.48,3657.8 ; KD46.4@3706.32,3660 KD46.4@3708.51,3657.8 ; KD59.4@4454.31,3660 KD59.4@4456.51,3657.8 ; KD70.4@5202.38,3660 KD70.4@5204.58,3657.8 ; R124.2@5564.97,1410 C56.1@5687.58,1410 ; KD77.4@5950.37,3660 KD77.4@5952.57,3657.8 ; KD88.4@6698.45,3660 KD88.4@6700.64,3657.8 ; KD104.4@8196.72,3657.8 8169.52,3685 7899.63,3685 7793.11,3578.48 7528,3578.48 KD97.4@7448.68,3657.8 7369.36,3578.48 6779.96,3578.48 KD88.4@6700.64,3657.8 ; KD18.4@1287.21,3657.8 1366.53,3578.48 1631.63,3578.48 1738.15,3685 2185.4,3685 KD29.4@2212.6,3657.8 ; KD29.4@2212.6,3657.8 2291.92,3578.48 2557.03,3578.48 2663.54,3685 2933.29,3685 KD35.4@2960.48,3657.8 ; KD35.4@2960.48,3657.8 3039.8,3578.48 3304.91,3578.48 3411.42,3685 3681.32,3685 KD46.4@3708.51,3657.8 ; KD46.4@3708.51,3657.8 3787.83,3578.48 4052.94,3578.48 4159.46,3685 4429.31,3685 KD59.4@4456.51,3657.8 ; KD59.4@4456.51,3657.8 4535.83,3578.48 4800.93,3578.48 4907.45,3685 5177.38,3685 KD70.4@5204.58,3657.8 ; KD70.4@5204.58,3657.8 5283.9,3578.48 5549,3578.48 5655.52,3685 5925.37,3685 KD77.4@5952.57,3657.8 ; KD77.4@5952.57,3657.8 6031.89,3578.48 6296.99,3578.48 6403.51,3685 6673.45,3685 KD88.4@6700.64,3657.8
  Bottom Layer w12: R124.2@5572.87,1418.92 v2@5592.57,1418.92
LED_B3: C49.1 KD3.4 KD19.4 KD30.4 KD36.4 KD52.4 KD60.4 KD71.4 KD78.4 KD89.4 KD98.4 KD105.4 R118.2 | length 11605.2
  Top Layer w8: KD60.4@4666.13,2903.25 KD60.4@4673.09,2910.2 ; KD71.4@5421.12,2910.2 5421.12,2883.97 5391.96,2854.81 5391.96,2637.56 4964.9,2210.5 4964.9,1750.1 5086.07,1628.93 5500.77,1628.93 5628.15,1501.56 5628.15,1380 5608.15,1360 5608.15,1250 v2(5598.15,1240)
  Bottom Layer w8: KD3.4@283.27,2910.2 363.47,2830 626.81,2830 734.21,2937.4 1368.28,2937.4 KD19.4@1395.48,2910.2 ; KD19.4@1393.28,2912.4 KD19.4@1395.48,2910.2 ; KD30.4@2426.74,2912.4 KD30.4@2428.94,2910.2 ; KD36.4@3174.82,2912.4 KD36.4@3177.01,2910.2 ; KD52.4@3922.85,2912.4 KD52.4@3925.04,2910.2 ; KD60.4@4670.89,2912.4 KD60.4@4673.09,2910.2 ; KD71.4@5418.92,2912.4 KD71.4@5421.12,2910.2 ; R118.2@5563.58,1231.39 C49.1@5687.58,1231.39 ; R118.2@5564.97,1230 v2@5598.15,1230 ; KD78.4@6166.95,2912.4 KD78.4@6169.15,2910.2 ; KD89.4@6914.99,2912.4 KD89.4@6917.18,2910.2 ; KD98.4@7663.02,2912.4 KD98.4@7665.21,2910.2 ; KD105.4@8413.21,2910.2 8386.01,2937.4 8116.16,2937.4 8008.76,2830 7745.42,2830 KD98.4@7665.21,2910.2 ; KD19.4@1395.48,2910.2 1475.68,2830 1739.02,2830 1846.42,2937.4 2401.74,2937.4 KD30.4@2428.94,2910.2 ; KD30.4@2428.94,2910.2 2509.14,2830 2772.48,2830 2879.88,2937.4 3149.82,2937.4 KD36.4@3177.01,2910.2 ; KD36.4@3177.01,2910.2 3257.22,2830 3520.55,2830 3627.95,2937.4 3897.85,2937.4 KD52.4@3925.04,2910.2 ; KD52.4@3925.04,2910.2 4005.25,2830 4268.59,2830 4348.79,2910.2 KD60.4@4673.09,2910.2 ; KD60.4@4673.09,2910.2 4753.29,2830 5016.63,2830 5124.03,2937.4 5393.92,2937.4 KD71.4@5421.12,2910.2 ; KD71.4@5421.12,2910.2 5501.32,2830 5764.66,2830 5872.06,2937.4 6141.95,2937.4 KD78.4@6169.15,2910.2 ; KD78.4@6169.15,2910.2 6254.35,2825 6507.69,2825 6620.09,2937.4 6889.99,2937.4 KD89.4@6917.18,2910.2 ; KD89.4@6917.18,2910.2 6997.39,2830 7260.72,2830 7368.12,2937.4 7638.02,2937.4 KD98.4@7665.21,2910.2
  Bottom Layer w12: R118.2@5572.87,1238.92 v2@5592.57,1238.92
LED_B4: C44.1 KD4.4 KD20.4 KD37.4 KD47.4 KD61.4 KD72.4 KD79.4 KD90.4 KD99.4 KD108.4 R112.2 | length 10464
  Top Layer w8: KD72.4@5066.76,2162.1 5066.76,1903.24 5277.43,1692.57 5529.58,1692.57 5703.15,1519 5703.15,1285 5628.15,1210 5588.15,1210 5568.15,1190 5568.15,1085 v2@5595.65,1057.5
  Bottom Layer w8: KD4.4@283.27,2162.1 361.89,2083.48 628.39,2083.48 734.21,2189.3 1453.15,2189.3 ; 1543.15,2189.3 1453.15,2189.3 ; KD20.4@1590.13,2164.3 KD20.4@1592.33,2162.1 ; KD37.4@2820.46,2164.3 KD37.4@2822.65,2162.1 ; KD47.4@3568.52,2164.3 KD47.4@3570.71,2162.1 ; KD61.4@4316.53,2164.3 KD61.4@4318.73,2162.1 ; KD72.4@5064.56,2164.3 KD72.4@5066.76,2162.1 ; R112.2@5563.58,1051.39 C44.1@5687.58,1051.39 ; R112.2@5564.97,1050 v2@5598.15,1050 ; KD90.4@6560.62,2164.3 KD90.4@6562.82,2162.1 ; KD99.4@7308.66,2164.3 KD99.4@7310.85,2162.1 ; KD108.4@8058.9,2162.1 8031.7,2189.3 7761.8,2189.3 7655.98,2083.48 7389.47,2083.48 KD99.4@7310.85,2162.1 ; 1453.15,2189.3 1565.13,2189.3 KD20.4@1592.33,2162.1 ; KD20.4@1592.33,2162.1 1670.95,2083.48 1937.45,2083.48 2043.27,2189.3 2795.46,2189.3 KD37.4@2822.65,2162.1 ; KD37.4@2822.65,2162.1 2901.27,2083.48 3167.78,2083.48 3273.59,2189.3 3543.52,2189.3 KD47.4@3570.71,2162.1 ; KD47.4@3570.71,2162.1 3654.33,2078.48 3910.84,2078.48 4021.66,2189.3 4291.53,2189.3 KD61.4@4318.73,2162.1 ; KD61.4@4318.73,2162.1 4397.35,2083.48 4663.85,2083.48 4769.67,2189.3 5039.56,2189.3 KD72.4@5066.76,2162.1 ; KD72.4@5066.76,2162.1 5145.38,2083.48 5411.88,2083.48 5517.7,2189.3 5787.59,2189.3 KD79.4@5814.79,2162.1 5893.41,2083.48 6159.91,2083.48 6265.73,2189.3 6535.62,2189.3 KD90.4@6562.82,2162.1 ; KD90.4@6562.82,2162.1 6641.44,2083.48 6907.95,2083.48 7013.76,2189.3 7283.66,2189.3 KD99.4@7310.85,2162.1
  Bottom Layer w12: R112.2@5572.87,1058.92 v2@5592.57,1058.92
  other v2: 5598.15,1060
LED_B5: C30.1 KD5.4 KD21.4 KD31.4 KD38.4 KD65.4 KD109.4 R93.1 | length 9782.2
  Top Layer w8: v2(6778.24,1171) 6832,1224.76 6832,1531.47 v2(6837,1536.47)
  Bottom Layer w8: KD5.4@283.27,1414.1 363.89,1333.48 626.39,1333.48 734.21,1441.3 1260.02,1441.3 KD21.4@1287.22,1414.1 ; KD21.4@1285.02,1416.3 KD21.4@1287.22,1414.1 ; KD31.4@2210.22,1416.3 KD31.4@2212.42,1414.1 ; KD38.4@3135.43,1416.3 KD38.4@3137.62,1414.1 ; 4615,1585.97 4687,1585.97 ; KD65.4@5950.39,1416.3 KD65.4@5952.59,1414.1 ; C30.1@6715,1179.89 R93.1@6820,1179.89 ; v2@6838,1530 6638.15,1530 6449.45,1341.3 6025.39,1341.3 KD65.4@5952.59,1414.1 ; v2@6841,1530 6953,1530 6973,1550 8408.59,1550 8517.29,1441.3 8740.36,1441.3 KD109.4@8767.56,1414.1 ; KD21.4@1287.22,1414.1 1367.84,1333.48 1630.34,1333.48 1738.16,1441.3 2185.22,1441.3 KD31.4@2212.42,1414.1 ; KD31.4@2212.42,1414.1 2293.04,1333.48 2555.55,1333.48 2663.36,1441.3 3110.43,1441.3 KD38.4@3137.62,1414.1 ; KD38.4@3137.62,1414.1 3218.24,1333.48 3480.75,1333.48 3733.23,1585.97 4687,1585.97 ; 4687,1585.97 5839.74,1585.97 5952.59,1473.12 KD65.4@5952.59,1414.1
  Bottom Layer w12: v2@6782.87,1168.92 R93.1@6820,1168.92
LED_B6: C37.1 KD6.4 KD22.4 KD32.4 KD48.4 KD62.4 KD66.4 LED1.4 LED3.4 LED4.4 R103.1 | length 15041.7
  Top Layer w8: v2(6795,1334.89) 6795,1357.85 6807,1369.85 6807,1577.47 6841.75,1612.22 7585.37,1612.22 7832,1858.85 7832,2233.85 8158.4,2560.25 8158.4,3020.07 7931.25,3247.22 7931.25,3762.22 7728.15,3965.32 7728.15,4462.62 7998.11,4732.57 8510.72,4732.57 9263.15,5485 10003.15,5485 KD6.4@10052.71,5435.44 ; LED1.4@16140.23,5281.47 16185,5281.47 v2(16192,5274.47) ; LED3.4@16675.23,5280 v2@16722,5280 ; LED4.4@17197,5280.43 v2(17197,5315)
  Bottom Layer w8: C37.1@6710,1351.39 R103.1@6811,1351.39 ; KD6.4@10047.07,5429.8 10116.87,5360 10392,5360 10461.8,5429.8 KD22.4@10794.99,5429.8 ; KD22.4@10795.1,5429.8 KD22.4@10794.99,5429.8 ; KD48.4@12566.77,5429.8 KD48.4@12566.92,5429.65 ; KD48.4@12566.92,5429.8 KD48.4@12566.92,5429.65 ; v2(17197,5315) 17154.8,5272.8 16734.2,5272.8 16727,5280 14397.15,5280 14307.35,5369.8 14122.83,5369.8 14062.83,5429.8 13746.8,5429.8 13677,5360 13384.6,5360 KD62.4@13314.8,5429.8 13020.41,5429.8 12950.6,5360 12636.57,5360 KD48.4@12566.92,5429.65 ; KD22.4@10794.99,5429.8 10864.8,5360 11137,5360 11206.8,5429.8 11543.02,5429.8 11612.83,5360 11867.15,5360 12027.35,5199.8 12431.8,5199.8 12566.92,5334.92 KD48.4@12566.92,5429.65
  Bottom Layer w12: v2@6797.87,1343.92 R103.1@6817.57,1343.92
  other v2: 16727,5275
LED_B7: C38.1 KD7.4 KD14.4 KD25.4 KD39.4 KD49.4 KD54.4 KD67.4 KD83.4 KD93.4 KD110.4 LED2.4 R104.2 | length 16602.1
  Top Layer w8: v2(7528.29,1413.48) 7601.29,1340.48 7601.29,1234.92 7914.73,921.48 9031.5,921.48 9169,1058.98 9169,1455.72 9104.72,1520 8719.73,1520 8646,1593.73 8646,2295.47 8903.85,2553.32 8903.85,3566.78 8528.15,3942.48 8528.15,4343.98 KD7.4@8590.38,4406.2 ; v2(15436.85,4530.7) 15481.85,4530.7 15533.29,4582.14 15533.29,4792.14 15606.85,4865.7 15606.85,5199.85 15596,5210.7 15596,5274.88 15607.85,5286.73 LED2.4@15628.5,5286.73
  Bottom Layer w8: R104.2@7489.17,1411.39 C38.1@7573.17,1411.39 ; KD7.4@8590.38,4406.2 8668.1,4328.48 8936.4,4328.48 9041.32,4433.4 9311.17,4433.4 ; 9311.25,4433.4 KD14.4@9338.45,4406.2 ; KD14.4@9336.17,4408.4 KD14.4@9338.37,4406.2 ; KD14.4@9336.25,4408.4 KD14.4@9338.45,4406.2 ; KD25.4@10084.24,4408.4 KD25.4@10086.44,4406.2 ; KD49.4@12566.77,4406.2 12521.74,4406.2 12378.34,4262.8 11421.77,4262.8 11381.77,4302.8 11292.28,4302.8 KD39.4@11188.88,4406.2 11124.35,4406.2 11111.42,4393.27 10518.26,4393.27 10453.47,4328.48 10164.16,4328.48 KD25.4@10086.44,4406.2 ; KD49.4@12572.97,4400 12637.97,4335 13243.64,4335 KD54.4@13314.84,4406.2 13391.04,4330 13929.81,4330 14006.01,4406.2 KD67.4@14062.87,4406.2 14139.07,4330 14738.15,4330 14967.63,4559.48 15408.06,4559.48 v2(15436.85,4530.7) 15461.85,4505.7 15461.85,4435.7 15491.85,4405.7 15806.85,4405.7 KD83.4@15826.85,4385.7 ; KD83.4@15834.7,4406.2 15920.91,4320 16188.79,4320 16274.99,4406.2 KD93.4@16582.53,4406.2 16668.73,4320 16913.15,4320 16999.35,4406.2 KD110.4@17330.59,4406.2 ; KD14.4@9338.45,4406.2 9416.17,4328.48 9684.47,4328.48 9789.39,4433.4 10059.24,4433.4 KD25.4@10086.44,4406.2
LED_B8: C31.1 KD8.4 KD15.4 KD26.4 KD40.4 KD50.4 KD55.4 KD68.4 KD73.4 KD84.4 KD94.4 KD106.4 R94.2 | length 16585.6
  Top Layer w8: v2@7523.1,1226 v2@7528.29,1226 ; v2@7528.32,1226.03 7890.75,863.6 9902.37,863.6 10078.15,1039.38 10078.15,1455 9993.15,1540 9606.39,1540 9417,1729.39 9417,2318.74 9629.89,2531.63 ; 9629.19,2532.34 9654.6,2557.75 9654.6,3619.62 KD15.4@9692.78,3657.8
  Bottom Layer w8: R94.2@7489.17,1240 R94.2@7490,1240 ; R94.2@7490,1229.89 C31.1@7580,1229.89 C31.1@7583.29,1229.89 ; KD8.4@8944.75,3657.8 9019.07,3583.48 9598.48,3583.48 9672.8,3657.8 KD15.4@9692.78,3657.8 9772.1,3578.48 10322.48,3578.48 10401.8,3657.8 KD26.4@10440.81,3657.8 10528.61,3570 11261,3570 11348.8,3657.8 KD40.4@11365.97,3657.8 11438.78,3585 11797,3585 12082,3870 12332,3870 12544.2,3657.8 KD50.4@12566.77,3657.8 12639.57,3585 13196,3585 13268.8,3657.8 KD55.4@13314.84,3657.8 13387.64,3585 13990.07,3585 KD68.4@14062.87,3657.8 14135.67,3585 14397,3585 14442,3630 14442,3835 14502.96,3895.96 14502.96,4180.96 14556.04,4234.04 14781.04,4234.04 14953.2,4406.2 KD73.4@15086.45,4406.2 15161.96,4330.7 15306.85,4330.7 15834.52,3803.02 KD84.4@15834.52,3657.8 ; KD84.4@15820.73,3671.6 KD84.4@15834.52,3657.8 ; KD94.4@16567.95,3671.6 KD94.4@16581.75,3657.8 ; KD94.4@16582.35,3657.8 KD94.4@16581.75,3657.8 ; KD106.4@17276.68,2932.43 17178.81,3030.31 17178.81,3247.1 16860.2,3565.7 16673.85,3565.7 KD94.4@16581.75,3657.8 ; KD84.4@15834.52,3657.8 15922.33,3570 16451.37,3570 16539.17,3657.8 KD94.4@16581.75,3657.8
  other v2: 7528.29,1228.48
LED_B9: C25.1 KD12.4 KD16.4 KD41.4 KD74.4 KD85.4 KD95.4 R87.2 | length 14289.6
  Top Layer w8: v2(7703.29,983.48) 7861.17,825.6 9918.11,825.6 10116.15,1023.64 10116.15,1470.74 10008.89,1578 9622.13,1578 9455,1745.13 9455,2303 9864.6,2712.6 9864.6,2865.48 KD16.4@9909.32,2910.2 ; v2(15001.85,3015.7) 15017,3030.85 15017,3463.19 15085.67,3531.86 KD74.4@15085.67,3657.8
  Bottom Layer w8: R87.2@7489.17,1060 R87.2@7490,1060 ; R87.2@7490,1049.89 7576.89,1049.89 7606.89,1019.89 7666.89,1019.89 v2(7703.29,983.48) ; KD12.4@9161.29,2910.2 9241.49,2830 9523.15,2830 9603.35,2910.2 KD16.4@9909.32,2910.2 9989.52,2830 10303.15,2830 10383.35,2910.2 KD41.4@11100.26,2910.2 11200.47,2810 11312,2810 11352,2770 12294,2770 12506,2982 14416,2982 14528,2870 14708.77,2870 14854.47,3015.7 v2(15001.85,3015.7) ; KD74.4@15085.67,3657.8 15167.08,3576.39 15316.76,3576.39 15481.77,3411.38 15481.77,3211.38 15782.95,2910.2 KD85.4@15834.7,2910.2 ; KD85.4@15820.91,2924 KD85.4@15834.7,2910.2 ; KD95.4@16582.53,2910.2 16539.35,2910.2 16459.15,2830 15914.91,2830 KD85.4@15834.7,2910.2
LED_B10: C13.1 KD9.4 KD23.4 KD42.4 KD56.4 KD80.4 KD86.4 KD100.4 KD107.4 R71.1 | length 11669
  Top Layer w8: v2(14292.26,2072.05) 14309,2055.31 14309,1642.77 14416.78,1535 14795,1535 14836.52,1493.48 14938.48,1493.48 v2(14950,1505) 15323.15,1505 15824.68,2006.53 KD86.4@15824.68,2174.11
  Bottom Layer w8: KD9.4@8806.93,2162.1 8885.55,2083.48 9454.64,2083.48 9533.26,2162.1 KD23.4@9554.96,2162.1 9646.37,2070.7 10791.85,2070.7 10883.26,2162.1 KD42.4@10913.15,2162.1 ; KD42.4@10923.07,2162.1 KD42.4@10913.15,2162.1 ; KD56.4@13314.81,2162.1 KD56.4@13331.65,2145.26 ; v2(14292.26,2072.05) 14284.31,2080 13396.91,2080 KD56.4@13331.65,2145.26 ; v2@14942,1505 C13.1@14942,1530 ; R71.1@14950,1439.89 v2(14950,1505) ; KD80.4@15086.03,2910.2 15176.23,2820 15452.15,2820 15746.73,2525.42 15746.73,2380.27 15824.68,2302.32 KD86.4@15824.68,2174.11 ; KD86.4@15810.89,2187.91 KD86.4@15824.68,2174.11 ; KD100.4@16568.74,2175.9 KD100.4@16570.53,2174.11 ; KD100.4@16572.51,2174.11 KD100.4@16570.53,2174.11 ; KD107.4@17276.48,1436.37 17179.6,1533.25 17179.6,1751.4 16861,2070 16674.64,2070 KD100.4@16582.54,2162.1 KD100.4@16570.53,2174.11 ; KD42.4@10913.15,2162.1 10994.56,2080.7 11659.04,2080.7 11962.97,1776.77 12827.77,1776.77 13196.26,2145.26 KD56.4@13331.65,2145.26 ; KD86.4@15824.68,2174.11 15908.8,2090 16175.24,2090 16259.35,2174.11 KD100.4@16570.53,2174.11
LED_B11: C18.1 KD10.4 KD27.4 KD43.4 KD51.4 KD57.4 KD69.4 KD81.4 KD91.4 KD101.4 LED5.4 R77.1 | length 14045.3
  Top Layer w8: v2(14452,1448) 14932,1448 ; 14897,1448 14932,1448 ; v2@15185.59,1448 14932,1448 ; v2@15185.71,1448 15416.78,1448 KD91.4@15450.67,1414.1 KD91.4@15434.78,1430 ; KD101.4@16582.72,1414.1 16605.47,1391.35 16605.47,1157.68 16763.51,999.64 16942.79,999.64 17033.15,1090 17033.15,4509.29 17422,4898.14 17422,4960.88 17489.6,5028.48 17624.6,5028.48 17687,5090.88 17687,5280 17693.73,5286.73 LED5.4@17718.5,5286.73
  Bottom Layer w8: KD10.4@9691.76,1414.1 9771.06,1334.8 10462.95,1334.8 10542.25,1414.1 KD27.4@10616.96,1414.1 ; KD27.4@10614.77,1416.3 KD27.4@10616.96,1414.1 ; KD43.4@11539.97,1416.3 KD43.4@11542.16,1414.1 ; KD51.4@12564.58,1416.3 12556.04,1424.84 12002.03,1424.84 11912,1334.8 11621.46,1334.8 KD43.4@11542.16,1414.1 ; KD51.4@12566.78,1414.1 12651.08,1329.8 12922,1329.8 13006.3,1414.1 KD57.4@13314.81,1414.1 13394.11,1334.8 13672,1334.8 13751.3,1414.1 KD69.4@14062.85,1414.1 14143.47,1333.48 14405.48,1333.48 14452,1380 v2(14452,1448) ; KD81.4@15076.65,2174.11 15170.77,2080 15300.41,2080 15471.08,1909.33 15471.08,1434.51 KD91.4@15450.67,1414.1 ; C18.1@15160,1519.89 R77.1@15160,1439.89 R77.1@15169.89,1430 ; R77.1@15172.59,1438.48 v2@15188.29,1438.48 ; KD91.4@15436.88,1427.9 KD91.4@15450.67,1414.1 ; KD101.4@16582.72,1414.1 15907.25,1414.1 15801.63,1308.48 15556.29,1308.48 KD91.4@15450.67,1414.1 ; KD27.4@10616.96,1414.1 10696.26,1334.8 10961.41,1334.8 11067.9,1441.3 11514.97,1441.3 KD43.4@11542.16,1414.1
  other v2: 15185.59,1445
LED_B12: C20.1 DD1.4 DD2.4 DD3.4 LED6.4 R78.2 | length 21983.6
  Top Layer w8: v2@131.85,605.7 162.51,605.7 DD3.4@181.98,625.17 ; v2@14482,801.47 14534,749.47 v2(15119,749.47) ; v2@15119,751.47 16767.62,751.47 17073.15,1057 17073.15,4492.72 17465.43,4885 17685.23,4885 LED6.4@17718.5,4851.73
  Bottom Layer w8: v2(131.85,610.7) 115.54,627.01 115.54,650.28 DD2.4@136.2,670.95 142.1,670.95 172.19,701.03 242.19,701.03 473.96,932.8 560.69,932.8 DD1.4@572.2,944.31 577.89,950 623.15,950 688.15,885 1633.15,885 1973.15,545 10622.48,545 10848.95,771.47 12138.72,771.47 12165.72,798.47 v2@14482,798.47 ; v2(15119,749.47) 15126,756.47 R78.2@15142,756.47 ; R78.2@15140.66,748.55 R78.2@15142.91,746.3 ; C20.1@15146,663.89 R78.2@15146,753.89
  other v2: 14482,794.47
LED_B13: C15.1 DD5.4 DD6.4 DD8.4 DD10.4 DD12.4 DD14.4 R72.2 | length 16592.8
  Top Layer w8: DD5.4@336.85,405.7 1616.85,405.7 v2(1626.85,395.7) ; DD6.4@3320.43,165.32 v2@3320.43,225 ; DD8.4@6318.27,100 v2@6318.27,168 ; DD10.4@9388.27,280.32 v2(9388.27,348.48) ; DD12.4@12672.27,340.11 DD12.4@12672.27,340.32 v2@12672.27,683.48 ; v2(13768.29,463.48) 13793.29,488.48 14609.6,488.48 ; 14588.93,488.48 14609.6,488.48 ; DD14.4@15370.72,425 DD14.4@15370.72,425.32 ; DD14.4@15371.6,425.32 15371.6,455.81 15332.61,494.8 14976.25,494.8 14969.93,488.48 14609.6,488.48
  Bottom Layer w8: v2(1626.85,395.7) 1647.55,375 3015,375 3177.39,212.61 3308.04,212.61 3365.43,270 5408.57,270 5536.57,398 5840.08,398 6079.08,159 7637.11,159 7698.11,220 9266.12,220 v2@9391.43,345.32 ; v2(9388.27,348.48) 9453.27,413.48 10708.29,413.48 10966.28,671.47 v2@12672.27,671.47 ; v2@12672.27,675.7 13501.2,675.7 13708.42,468.48 v2@13768.29,468.48 ; v2@12672.27,680.7 12669.48,680.7 v2@12672.27,683.48 ; C15.1@14936,663.89 14950.6,663.89 14971.4,643.08 ; R72.2@14936,753.89 14941,748.89 C15.1@14941,668.89 ; v2@14971.4,483.95 14971.4,643.08 ; 14971.4,557.48 14971.4,643.08
  other v2: 6326.43,168 3322.43,225 14969.93,491.48 12673.27,679.47
LED_B14: C9.1 DD4.4 DD7.4 DD9.4 DD11.4 DD13.4 DD15.4 DD16.4 DD17.4 DD18.4 R66.2 | length 18174.2
  Top Layer w8: DD4.4@1818.27,260.32 v2@1818.27,300 ; DD7.4@4808.27,100.42 v2(4808.27,197.15) ; DD9.4@7808.27,125.49 7808.27,143.46 v2@7818.29,153.48 ; DD11.4@10874.6,273.48 v2@10874.6,402.47 ; DD13.4@13854.6,280.32 v2(13854.6,318.48) 13854.6,323.48 13856.12,325 13867.63,313.48 14689.93,313.48 14699.93,303.48 16798.29,303.48 16868.6,373.79 DD15.4@16868.6,421.32 ; DD15.4@16868.6,440 DD15.4@16868.6,421.32 ; DD17.4@17628.98,700.83 17678.15,651.66 17678.15,595 v2(17628.15,545) 17543.85,460.7 17019.36,460.7 16875.36,460.7 16868.6,453.94 DD15.4@16868.6,421.32
  Bottom Layer w8: v2(1818.15,300) 1832,313.85 2986.15,313.85 3147.39,152.61 3361.27,152.61 3400.12,191.47 4802.58,191.47 v2@4804.6,193.48 ; v2@4808.27,198.48 5439.33,198.48 5569.33,328.48 5809.87,328.48 6039.41,98.94 7774.94,98.94 v2(7826,150) 7836,160 9311.12,160 9504.6,353.48 10828.61,353.48 v2(10877.59,402.47) 10877.59,468.05 11021,611.47 13446.08,611.47 13732.35,325.2 v2@13856.12,325.2 ; v2@14690.6,307.48 14690.6,643.08 14711.4,663.89 C9.1@14726,663.89 R66.2@14726,753.89 ; DD18.4@17163.51,841.41 17171.93,832.98 17338.22,832.98 DD16.4@17582.88,588.32 v2@17619.68,551.53
  other v2: 14689.93,316.48
LED_G0: C46.1 KD11.3 KD13.3 KD24.3 KD33.3 KD44.3 KD53.3 KD63.3 KD75.3 KD82.3 KD92.3 KD102.3 R115.1 | length 15569.6
  Top Layer w8: v2(4867.57,1093.92) 4894.85,1121.19 4894.85,1182.2 4868.85,1208.2 4851.74,1208.2 4809.6,1250.34 4809.6,2265.43 5233.97,2689.8 5233.97,3070.95 5062.01,3242.91 5062.01,3700.91 4779.06,3983.86 4779.06,4425.27 4824.79,4471 5063,4471 5964.8,5372.8 6031.77,5372.8 6061.77,5402.8 6061.77,5452.8 6091.77,5482.8 6160.57,5482.8 KD63.3@6213.57,5429.8
  Bottom Layer w8: KD11.3@583.27,5429.8 611.8,5429.8 703.47,5521.47 1317.9,5521.47 KD13.3@1409.57,5429.8 1945.34,5429.8 2037,5521.47 2735.9,5521.47 KD24.3@2827.56,5429.8 2912.76,5515 3490.37,5515 KD33.3@3575.56,5429.8 3665.76,5520 4233.37,5520 KD44.3@4323.56,5429.8 4604.23,5429.8 4694.43,5520 4981.37,5520 KD53.3@5071.57,5429.8 5103.58,5429.8 5195.24,5521.47 6121.91,5521.47 KD63.3@6213.57,5429.8 6293.77,5510 6881.03,5510 KD75.3@6961.23,5429.8 7051.43,5520 7606,5520 7696.2,5429.8 KD82.3@7709.31,5429.8 7789.51,5510 8397.15,5510 8457.35,5449.8 KD92.3@8457.35,5429.8 8508.84,5378.3 9125.2,5378.3 9251.9,5505 9523.96,5505 KD102.3@9599.16,5429.8 ; C46.1@4812,1110.31 4885,1110.31 R115.1@4896,1110.31
  Bottom Layer w12: v2@4869.69,1095 R115.1@4885,1110.31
